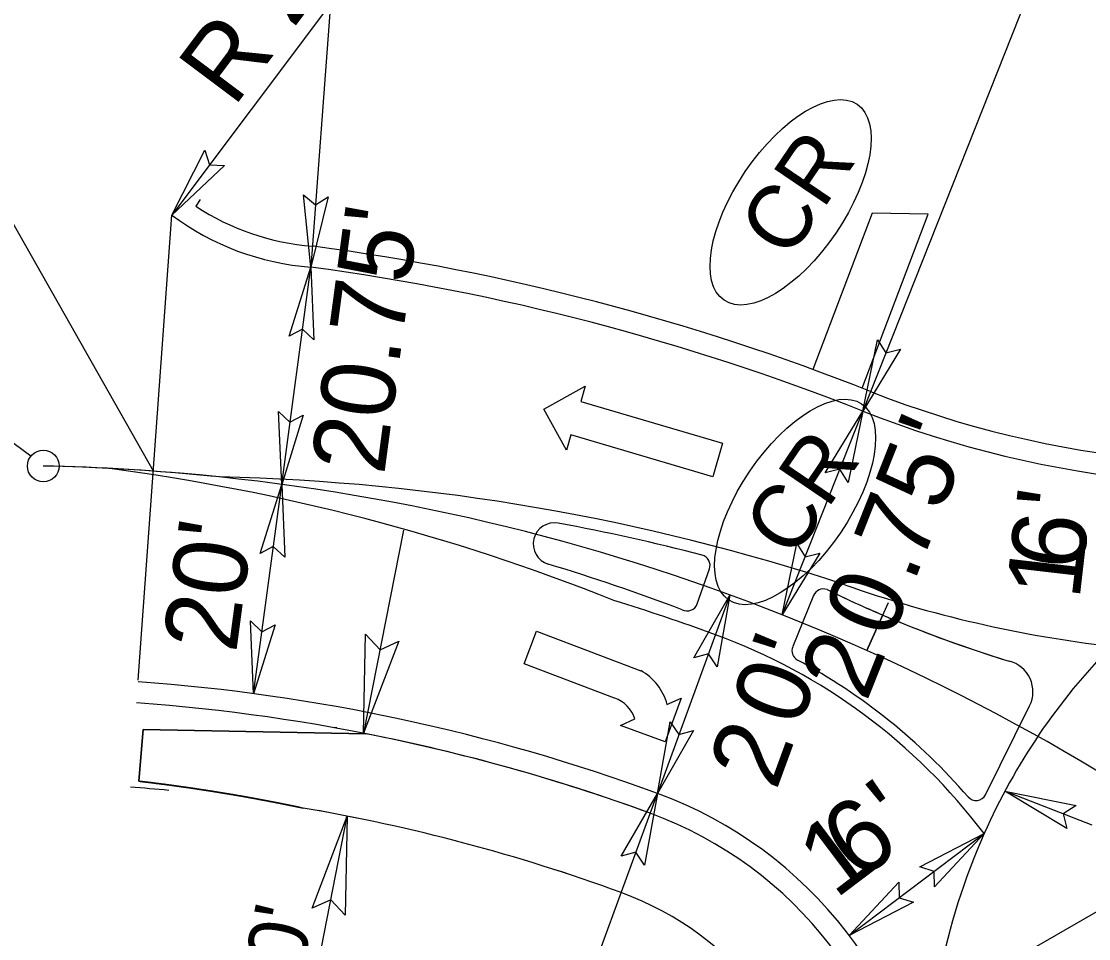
# Model space of a CAD drawing. Extents: x 1975573 to 1977432, y 778300 to 780514.
# Drawn here: x 1976181.7 to 1976308, y 779472 to 779580.6 of the extents above; entities that cross this region are included whole.
import ezdxf

# ---------------------------------------------------------------- set-up
doc = ezdxf.new("R2010")
doc.units = 0
for name, color, linetype in [('Prop Conc 2ft 6in Curb and Gutter', 7, 'Continuous'), ('Prop Conc 4in Sidewalk', 7, 'Continuous'), ('Prop Conc 5in Monolithic Keyed In Island', 7, 'Continuous'), ('Prop Dimension', 7, 'Continuous'), ('Prop Dimension Text', 7, 'Continuous'), ('Prop EOT', 7, 'Continuous'), ('Prop Horizontal Alignment', 7, 'Continuous'), ('Prop Horizontal Alignment Station Label', 7, 'Continuous'), ('Prop Horizontal Alignment Tick Small', 7, 'Continuous'), ('Prop Lane Arrow CELL', 7, 'Continuous'), ('Prop Lane Lines', 7, 'Continuous'), ('Prop Terminator CELL', 7, 'Continuous'), ('Prop WCC CELL', 7, 'Continuous'), ('Typical Terminator CELL', 7, 'Continuous')]:
    doc.layers.add(name, color=color, linetype=linetype)

# ---------------------------------------------------------------- blocks, each defined once
blk = doc.blocks.new('TERMINATOR')
at = {"layer": 'Typical Terminator CELL'}
blk.add_lwpolyline([(-0.4687, 0.0807), (0, 0), (-0.4713, -0.0833), (-0.4114, 0)], close=True, dxfattribs=at)

msp = doc.modelspace()

# ---------------------------------------------------------------- linework, layer by layer
at = {"layer": 'Prop Conc 2ft 6in Curb and Gutter'}
msp.add_line((1976202.88, 779559.51), (1976202.36, 779558.72), dxfattribs=at)
for centre, radius, start, end in [((1976218.28, 779582.67), 28.75, 236.3985, 265.7267), ((1976179.17, 779276.72), 279.73, 68.3898, 82.3776), ((1976327.31, 779650.68), 122.5, 248.3898, 280.6337), ((1976179.17, 779276.72), 223.8, 69.8927, 85.8568), ((1976239.78, 779442.27), 47.5, 5.4373, 69.8927)]:
    msp.add_arc(centre, radius, start, end, dxfattribs=at)
at = {"layer": 'Prop Conc 4in Sidewalk'}
for p, q in [((1976282.37, 779557.88), (1976275.36, 779539.4)), ((1976281.21, 779537.18), (1976289.01, 779557.77)), ((1976289.01, 779557.77), (1976282.37, 779557.88)), ((1976195.6, 779490.67), (1976196.11, 779496.78)), ((1976196.11, 779496.78), (1976195.6, 779490.67)), ((1976196.11, 779496.78), (1976222.47, 779496.29)), ((1976222.47, 779496.29), (1976196.11, 779496.78)), ((1976198.7, 779490.53), (1976198.7, 779490.53))]:
    msp.add_line(p, q, dxfattribs=at)
for centre, radius, start, end in [((1976179.17, 779276.72), 223.8, 69.8927, 78.8445), ((1976179.17, 779276.72), 223.8, 69.8927, 78.8445), ((1976179.17, 779276.72), 213.8, 84.6358, 85.8568), ((1976179.17, 779276.72), 213.8, 69.8927, 80.343), ((1976179.17, 779276.72), 213.8, 69.8927, 80.342), ((1976239.78, 779442.27), 47.5, 5.4373, 69.8927), ((1976239.78, 779442.27), 47.5, 5.4373, 69.8927), ((1976239.78, 779442.27), 37.5, 5.4373, 69.8927), ((1976239.78, 779442.27), 37.5, 5.4373, 69.8927)]:
    msp.add_arc(centre, radius, start, end, dxfattribs=at)
for points in [[(1976215.04, 779487.49), (1976214.87, 779487.53), (1976214.69, 779487.56), (1976214.52, 779487.6), (1976214.43, 779487.62), (1976214.35, 779487.63), (1976214.26, 779487.65), (1976214.17, 779487.67), (1976214.09, 779487.69), (1976214, 779487.71), (1976213.91, 779487.72), (1976213.83, 779487.74), (1976213.74, 779487.76), (1976213.65, 779487.78), (1976213.57, 779487.8), (1976213.48, 779487.81), (1976213.39, 779487.83), (1976213.31, 779487.85), (1976213.22, 779487.87), (1976213.13, 779487.88), (1976213.05, 779487.9), (1976212.96, 779487.92), (1976212.87, 779487.94), (1976212.78, 779487.95), (1976212.7, 779487.97), (1976212.61, 779487.99), (1976212.52, 779488), (1976212.44, 779488.02), (1976212.35, 779488.04), (1976212.26, 779488.06), (1976212.18, 779488.07), (1976212.09, 779488.09), (1976212, 779488.11), (1976211.91, 779488.12), (1976211.83, 779488.14), (1976211.74, 779488.16), (1976211.65, 779488.18), (1976211.57, 779488.19), (1976211.48, 779488.21), (1976211.39, 779488.23), (1976211.31, 779488.24), (1976211.22, 779488.26), (1976211.13, 779488.28), (1976211.04, 779488.29), (1976210.96, 779488.31), (1976210.87, 779488.33), (1976210.78, 779488.34), (1976210.7, 779488.36), (1976210.61, 779488.38), (1976210.52, 779488.39), (1976210.43, 779488.41), (1976210.35, 779488.43), (1976210.26, 779488.44), (1976210.17, 779488.46), (1976210.09, 779488.47), (1976210, 779488.49), (1976209.91, 779488.51), (1976209.82, 779488.52), (1976209.74, 779488.54), (1976209.65, 779488.56), (1976209.56, 779488.57), (1976209.48, 779488.59), (1976209.39, 779488.6), (1976209.3, 779488.62), (1976209.21, 779488.64), (1976209.13, 779488.65), (1976209.04, 779488.67), (1976208.95, 779488.68), (1976208.86, 779488.7), (1976208.78, 779488.71), (1976208.69, 779488.73), (1976208.6, 779488.75), (1976208.52, 779488.76), (1976208.43, 779488.78), (1976208.34, 779488.79), (1976208.25, 779488.81), (1976208.17, 779488.82), (1976208.08, 779488.84), (1976207.99, 779488.85), (1976207.9, 779488.87), (1976207.82, 779488.89), (1976207.73, 779488.9), (1976207.64, 779488.92), (1976207.55, 779488.93), (1976207.47, 779488.95), (1976207.38, 779488.96), (1976207.29, 779488.98), (1976207.2, 779488.99), (1976207.12, 779489.01), (1976207.03, 779489.02), (1976206.94, 779489.04), (1976206.86, 779489.05), (1976206.77, 779489.07), (1976206.68, 779489.08), (1976206.59, 779489.1), (1976206.51, 779489.11), (1976206.42, 779489.13), (1976206.33, 779489.14), (1976206.24, 779489.16), (1976206.16, 779489.17), (1976206.07, 779489.18), (1976205.98, 779489.2), (1976205.89, 779489.21), (1976205.8, 779489.23), (1976205.72, 779489.24), (1976205.63, 779489.26), (1976205.54, 779489.27), (1976205.45, 779489.29), (1976205.37, 779489.3), (1976205.28, 779489.31), (1976205.19, 779489.33), (1976205.1, 779489.34), (1976205.02, 779489.36), (1976204.93, 779489.37), (1976204.84, 779489.39), (1976204.75, 779489.4), (1976204.67, 779489.41), (1976204.58, 779489.43), (1976204.49, 779489.44), (1976204.4, 779489.46), (1976204.32, 779489.47), (1976204.23, 779489.48), (1976204.14, 779489.5), (1976204.05, 779489.51), (1976203.96, 779489.53), (1976203.88, 779489.54), (1976203.79, 779489.55), (1976203.7, 779489.57), (1976203.61, 779489.58), (1976203.53, 779489.59), (1976203.44, 779489.61), (1976203.35, 779489.62), (1976203.26, 779489.63), (1976203.18, 779489.65), (1976203.09, 779489.66), (1976203, 779489.67), (1976202.91, 779489.69), (1976202.82, 779489.7), (1976202.74, 779489.71), (1976202.65, 779489.73), (1976202.56, 779489.74), (1976202.47, 779489.75), (1976202.38, 779489.77), (1976202.3, 779489.78), (1976202.21, 779489.79), (1976202.12, 779489.81), (1976202.03, 779489.82), (1976201.95, 779489.83), (1976201.86, 779489.84), (1976201.77, 779489.86), (1976201.68, 779489.87), (1976201.59, 779489.88), (1976201.51, 779489.9), (1976201.42, 779489.91), (1976201.33, 779489.92), (1976201.24, 779489.93), (1976201.15, 779489.95), (1976201.07, 779489.96), (1976200.98, 779489.97), (1976200.89, 779489.98), (1976200.8, 779490), (1976200.71, 779490.01), (1976200.63, 779490.02), (1976200.54, 779490.03), (1976200.45, 779490.05), (1976200.36, 779490.06), (1976200.27, 779490.07), (1976200.19, 779490.08), (1976200.1, 779490.09), (1976200.01, 779490.11), (1976199.92, 779490.12), (1976199.83, 779490.13), (1976199.75, 779490.14), (1976199.66, 779490.16), (1976199.57, 779490.17), (1976199.48, 779490.18), (1976199.39, 779490.19), (1976199.31, 779490.2), (1976199.22, 779490.21), (1976199.13, 779490.23), (1976199.04, 779490.24), (1976198.95, 779490.25), (1976198.87, 779490.26), (1976198.78, 779490.27), (1976198.69, 779490.28), (1976198.6, 779490.3), (1976198.51, 779490.31), (1976198.43, 779490.32), (1976198.34, 779490.33), (1976198.25, 779490.34), (1976198.16, 779490.35), (1976198.07, 779490.36), (1976197.98, 779490.38), (1976197.9, 779490.39), (1976197.81, 779490.4), (1976197.72, 779490.41), (1976197.63, 779490.42), (1976197.54, 779490.43), (1976197.46, 779490.44), (1976197.37, 779490.45), (1976197.28, 779490.47), (1976197.19, 779490.48), (1976197.1, 779490.49), (1976197.01, 779490.5), (1976196.93, 779490.51), (1976196.84, 779490.52), (1976196.75, 779490.53), (1976196.66, 779490.54), (1976196.57, 779490.55), (1976196.49, 779490.56), (1976196.4, 779490.57), (1976196.31, 779490.58), (1976196.22, 779490.59), (1976196.13, 779490.6), (1976196.04, 779490.62), (1976195.96, 779490.63), (1976195.87, 779490.64), (1976195.78, 779490.65), (1976195.69, 779490.66), (1976195.6, 779490.67)], [(1976195.6, 779490.67), (1976195.69, 779490.66), (1976195.78, 779490.65), (1976195.87, 779490.64), (1976195.96, 779490.63), (1976196.04, 779490.62), (1976196.13, 779490.6), (1976196.22, 779490.59), (1976196.31, 779490.58), (1976196.4, 779490.57), (1976196.49, 779490.56), (1976196.57, 779490.55), (1976196.66, 779490.54), (1976196.75, 779490.53), (1976196.84, 779490.52), (1976196.93, 779490.51), (1976197.01, 779490.5), (1976197.1, 779490.49), (1976197.19, 779490.48), (1976197.28, 779490.47), (1976197.37, 779490.45), (1976197.46, 779490.44), (1976197.54, 779490.43), (1976197.63, 779490.42), (1976197.72, 779490.41), (1976197.81, 779490.4), (1976197.9, 779490.39), (1976197.98, 779490.38), (1976198.07, 779490.36), (1976198.16, 779490.35), (1976198.25, 779490.34), (1976198.34, 779490.33), (1976198.43, 779490.32), (1976198.51, 779490.31), (1976198.6, 779490.3), (1976198.69, 779490.28), (1976198.78, 779490.27), (1976198.87, 779490.26), (1976198.95, 779490.25), (1976199.04, 779490.24), (1976199.13, 779490.23), (1976199.22, 779490.21), (1976199.31, 779490.2), (1976199.39, 779490.19), (1976199.48, 779490.18), (1976199.57, 779490.17), (1976199.66, 779490.16), (1976199.75, 779490.14), (1976199.83, 779490.13), (1976199.92, 779490.12), (1976200.01, 779490.11), (1976200.1, 779490.09), (1976200.19, 779490.08), (1976200.27, 779490.07), (1976200.36, 779490.06), (1976200.45, 779490.05), (1976200.54, 779490.03), (1976200.63, 779490.02), (1976200.71, 779490.01), (1976200.8, 779490), (1976200.89, 779489.98), (1976200.98, 779489.97), (1976201.07, 779489.96), (1976201.15, 779489.95), (1976201.24, 779489.93), (1976201.33, 779489.92), (1976201.42, 779489.91), (1976201.51, 779489.9), (1976201.59, 779489.88), (1976201.68, 779489.87), (1976201.77, 779489.86), (1976201.86, 779489.84), (1976201.95, 779489.83), (1976202, 779489.82), (1976202.06, 779489.82), (1976202.11, 779489.81)], [(1976202.11, 779489.81), (1976202.15, 779489.8), (1976202.18, 779489.8), (1976202.21, 779489.79), (1976202.3, 779489.78), (1976202.38, 779489.77), (1976202.47, 779489.75), (1976202.56, 779489.74), (1976202.65, 779489.73), (1976202.74, 779489.71), (1976202.82, 779489.7), (1976202.91, 779489.69), (1976203, 779489.67), (1976203.09, 779489.66), (1976203.18, 779489.65), (1976203.26, 779489.63), (1976203.35, 779489.62), (1976203.44, 779489.61), (1976203.53, 779489.59), (1976203.61, 779489.58), (1976203.7, 779489.57), (1976203.79, 779489.55), (1976203.88, 779489.54), (1976203.96, 779489.53), (1976204.05, 779489.51), (1976204.14, 779489.5), (1976204.23, 779489.48), (1976204.32, 779489.47), (1976204.4, 779489.46), (1976204.49, 779489.44), (1976204.58, 779489.43), (1976204.67, 779489.41), (1976204.75, 779489.4), (1976204.84, 779489.39), (1976204.93, 779489.37), (1976205.02, 779489.36), (1976205.1, 779489.34), (1976205.19, 779489.33), (1976205.28, 779489.31), (1976205.37, 779489.3), (1976205.45, 779489.29), (1976205.54, 779489.27), (1976205.63, 779489.26), (1976205.72, 779489.24), (1976205.8, 779489.23), (1976205.89, 779489.21), (1976205.98, 779489.2), (1976206.07, 779489.18), (1976206.16, 779489.17), (1976206.24, 779489.16), (1976206.33, 779489.14), (1976206.42, 779489.13), (1976206.51, 779489.11), (1976206.59, 779489.1), (1976206.68, 779489.08), (1976206.77, 779489.07), (1976206.86, 779489.05), (1976206.94, 779489.04), (1976207.03, 779489.02), (1976207.12, 779489.01), (1976207.2, 779488.99), (1976207.29, 779488.98), (1976207.38, 779488.96), (1976207.47, 779488.95), (1976207.55, 779488.93), (1976207.64, 779488.92), (1976207.73, 779488.9), (1976207.82, 779488.89), (1976207.9, 779488.87), (1976207.99, 779488.85), (1976208.08, 779488.84), (1976208.17, 779488.82), (1976208.25, 779488.81), (1976208.34, 779488.79), (1976208.43, 779488.78), (1976208.52, 779488.76), (1976208.54, 779488.76), (1976208.57, 779488.75), (1976208.6, 779488.75)], [(1976208.6, 779488.75), (1976208.66, 779488.74), (1976208.72, 779488.73), (1976208.78, 779488.71), (1976208.86, 779488.7), (1976208.95, 779488.68), (1976209.04, 779488.67), (1976209.13, 779488.65), (1976209.21, 779488.64), (1976209.3, 779488.62), (1976209.39, 779488.6), (1976209.48, 779488.59), (1976209.56, 779488.57), (1976209.65, 779488.56), (1976209.74, 779488.54), (1976209.82, 779488.52), (1976209.91, 779488.51), (1976210, 779488.49), (1976210.09, 779488.47), (1976210.17, 779488.46), (1976210.26, 779488.44), (1976210.35, 779488.43), (1976210.43, 779488.41), (1976210.52, 779488.39), (1976210.61, 779488.38), (1976210.7, 779488.36), (1976210.78, 779488.34), (1976210.87, 779488.33), (1976210.96, 779488.31), (1976211.04, 779488.29), (1976211.13, 779488.28), (1976211.22, 779488.26), (1976211.31, 779488.24), (1976211.39, 779488.23), (1976211.48, 779488.21), (1976211.57, 779488.19), (1976211.65, 779488.18), (1976211.74, 779488.16), (1976211.83, 779488.14), (1976211.91, 779488.12), (1976212, 779488.11), (1976212.09, 779488.09), (1976212.18, 779488.07), (1976212.26, 779488.06), (1976212.35, 779488.04), (1976212.44, 779488.02), (1976212.52, 779488), (1976212.61, 779487.99), (1976212.7, 779487.97), (1976212.78, 779487.95), (1976212.87, 779487.94), (1976212.96, 779487.92), (1976213.05, 779487.9), (1976213.13, 779487.88), (1976213.22, 779487.87), (1976213.31, 779487.85), (1976213.39, 779487.83), (1976213.48, 779487.81), (1976213.57, 779487.8), (1976213.65, 779487.78), (1976213.74, 779487.76), (1976213.83, 779487.74), (1976213.91, 779487.72), (1976214, 779487.71), (1976214.09, 779487.69), (1976214.17, 779487.67), (1976214.26, 779487.65), (1976214.35, 779487.63), (1976214.43, 779487.62), (1976214.52, 779487.6), (1976214.69, 779487.56), (1976214.87, 779487.53), (1976215.04, 779487.49)]]:
    msp.add_open_spline(points, degree=3, dxfattribs=at)
at = {"layer": 'Prop Conc 5in Monolithic Keyed In Island'}
for p, q in [((1976261.67, 779511.64), (1976263.13, 779515.8)), ((1976275.46, 779512.64), (1976272.98, 779506.59)), ((1976295.8, 779489.07), (1976301.02, 779499.59))]:
    msp.add_line(p, q, dxfattribs=at)
for points in [[(1976261.67, 779511.64), (1976263.13, 779515.8)], [(1976275.46, 779512.64), (1976272.98, 779506.59)], [(1976283.64, 779510.34), (1976281.76, 779506.13), (1976283.64, 779510.34)], [(1976295.8, 779489.07), (1976301.02, 779499.59)]]:
    msp.add_lwpolyline(points, dxfattribs=at)
for centre, radius, start, end in [((1976244.78, 779518.75), 2.5, 79.4395, 253.1009), ((1976244.78, 779518.75), 2.5, 79.4395, 253.1009), ((1976198.82, 779272.22), 253.28, 75.4924, 79.4395), ((1976198.82, 779272.22), 253.28, 75.4924, 79.4395), ((1976261.95, 779516.21), 1.25, 340.6492, 75.4924), ((1976261.95, 779516.21), 1.25, 340.6492, 75.4924), ((1976171.22, 779276.62), 250.56, 69.2746, 73.1009), ((1976171.22, 779276.62), 250.56, 69.2746, 73.1009), ((1976276.61, 779512.17), 1.25, 69.8958, 157.7992), ((1976276.61, 779512.17), 1.25, 69.8958, 157.7992), ((1976341.8, 779646.63), 148.19, 244.0891, 253.0553), ((1976341.8, 779646.63), 148.19, 244.0891, 246.8935), ((1976260.5, 779512.06), 1.25, 241.0006, 340.6492), ((1976260.5, 779512.06), 1.25, 241.0006, 340.6492), ((1976341.8, 779646.63), 148.19, 246.8935, 253.0553), ((1976274.14, 779506.11), 1.25, 157.7992, 241.7102), ((1976274.14, 779506.11), 1.25, 157.7992, 241.7102), ((1976239.78, 779442.27), 71.25, 40.7773, 61.7102), ((1976239.78, 779442.27), 71.25, 40.7773, 61.7102), ((1976297.66, 779501.25), 3.75, 333.6015, 75.4103), ((1976297.66, 779501.25), 3.75, 333.6015, 75.4103), ((1976294.68, 779489.63), 1.25, 220.7773, 333.6015), ((1976294.68, 779489.63), 1.25, 220.7773, 333.6015)]:
    msp.add_arc(centre, radius, start, end, dxfattribs=at)
at = {"layer": 'Prop Dimension'}
for p, q in [((1976212.51, 779525.8), (1976215.95, 779551.51)), ((1976209.19, 779501.02), (1976212.51, 779525.8)), ((1976226.94, 779520.38), (1976222.2, 779496.34)), ((1976219.04, 779496.97), (1976218.77, 779497.02)), ((1976211, 779439.54), (1976220.27, 779486.53)), ((1976217.1, 779487.16), (1976216.83, 779487.21))]:
    msp.add_line(p, q, dxfattribs=at)
at = {"layer": 'Prop Dimension Text'}
for p, q in [((1976327.31, 779650.68), (1976281.28, 779534.47)), ((1976218.28, 779582.67), (1976199.52, 779557.67)), ((1976218.28, 779582.67), (1976215.95, 779551.51)), ((1976271.72, 779510.36), (1976281.28, 779534.47)), ((1976265.56, 779512.7), (1976256.97, 779489.23)), ((1976239.78, 779442.27), (1976256.97, 779489.23)), ((1976308.4, 779485.46), (1976298.09, 779489.5)), ((1976279.68, 779472.41), (1976295.63, 779484.47))]:
    msp.add_line(p, q, dxfattribs=at)
at = {"layer": 'Prop EOT'}
msp.add_line((1976195.54, 779502.62), (1976199.52, 779557.67), dxfattribs=at)
for centre, radius, start, end in [((1976218.28, 779582.67), 31.25, 233.1295, 265.7267), ((1976179.17, 779276.72), 277.23, 68.3898, 82.3776), ((1976327.31, 779650.68), 125, 248.3898, 280.6337), ((1976179.17, 779276.72), 226.3, 69.8927, 85.8568), ((1976239.78, 779442.27), 50, 5.4373, 69.8927)]:
    msp.add_arc(centre, radius, start, end, dxfattribs=at)
at = {"layer": 'Prop Horizontal Alignment'}
for centre, radius, start, end in [((1978303.2, 778082.63), 2375, 135.73946, 152.1381), ((1976179.17, 779276.72), 251.3, 55.1768, 88.8319), ((1976179.17, 779276.72), 251.3, 55.1768, 88.8319), ((1976179.17, 779276.72), 251.3, 55.1768, 88.8319), ((1976179.17, 779276.72), 251.3, 55.1768, 88.8319), ((1976179.17, 779276.72), 251.3, 55.1768, 88.8319)]:
    msp.add_arc(centre, radius, start, end, dxfattribs=at)
at = {"layer": 'Prop Horizontal Alignment Station Label'}
for p, q in [((1976197.33, 779527.36), (1976158.07, 779596.64)), ((1976182.82, 779529.12), (1976094.98, 779594.64)), ((1976321.01, 779482.16), (1976180.99, 779401.56))]:
    msp.add_line(p, q, dxfattribs=at)
msp.add_circle((1976184.3, 779527.97), 1.88, dxfattribs=at)
msp.add_circle((1976184.3, 779527.97), 1.88, dxfattribs=at)
at = {"layer": 'Prop Horizontal Alignment Tick Small'}
msp.add_line((1976281.76, 779506.13), (1976284.31, 779511.83), dxfattribs=at)
msp.add_line((1976281.76, 779506.13), (1976284.31, 779511.83), dxfattribs=at)
at = {"layer": 'Prop Lane Arrow CELL'}
for p, q in [((1976243.52, 779534.69), (1976248.43, 779537.41)), ((1976248.43, 779537.41), (1976247.9, 779535.61)), ((1976247.9, 779535.61), (1976264.69, 779530.66)), ((1976246.2, 779529.86), (1976243.52, 779534.69)), ((1976246.73, 779531.66), (1976246.2, 779529.86)), ((1976263.52, 779526.7), (1976246.73, 779531.66)), ((1976264.69, 779530.66), (1976263.52, 779526.7)), ((1976241.21, 779504.57), (1976242.68, 779508.43)), ((1976242.68, 779508.43), (1976255.01, 779503.73)), ((1976251.9, 779500.5), (1976241.21, 779504.57)), ((1976259.79, 779500.5), (1976257.89, 779495.34)), ((1976258.1, 779499.74), (1976259.79, 779500.5)), ((1976252.61, 779497.28), (1976254.31, 779498.04)), ((1976257.89, 779495.34), (1976252.61, 779497.28))]:
    msp.add_line(p, q, dxfattribs=at)
for centre, radius, start, end in [((1976251.78, 779498.04), 6.57, 15.1417, 60.4534), ((1976250.46, 779496.69), 4.09, 19.4713, 69.1294)]:
    msp.add_arc(centre, radius, start, end, dxfattribs=at)
at = {"layer": 'Prop Lane Lines'}
for centre, radius, start, end in [((1976179.17, 779276.72), 251.3, 84.2095, 88.8319), ((1976159.31, 779280.17), 249.67, 68.2497, 82.4998), ((1976199.38, 779272.11), 254.63, 71.7429, 88.6885), ((1976327.31, 779650.68), 145, 250.6014, 263.4132), ((1976179.17, 779276.72), 246.3, 69.8927, 72.8425), ((1976239.78, 779442.27), 70, 37.07, 69.8927), ((1976364.22, 779454.12), 75, 135.5489, 156.1292), ((1976364.16, 779453.7), 75.1, 155.8173, 182.5752)]:
    msp.add_arc(centre, radius, start, end, dxfattribs=at)
at = {"layer": 'Prop Terminator CELL'}
for points in [[(1976205.75, 779563.55), (1976199.52, 779557.67), (1976203.42, 779565.36), (1976203.97, 779563.6)], [(1976218.02, 779559.81), (1976215.95, 779551.51), (1976215.08, 779560.08), (1976216.5, 779558.89)], [(1976213.39, 779543.34), (1976215.95, 779551.51), (1976216.31, 779542.9), (1976214.96, 779544.17)], [(1976285.73, 779541.78), (1976281.28, 779534.47), (1976283.01, 779542.91), (1976284, 779541.36)], [(1976215.07, 779533.97), (1976212.51, 779525.8), (1976212.14, 779534.41), (1976213.49, 779533.14)], [(1976276.82, 779527.16), (1976281.28, 779534.47), (1976279.55, 779526.03), (1976278.55, 779527.58)], [(1976209.95, 779517.63), (1976212.51, 779525.8), (1976212.87, 779517.19), (1976211.52, 779518.46)], [(1976276.18, 779517.67), (1976271.72, 779510.36), (1976273.45, 779518.8), (1976274.45, 779517.24)], [(1976261.3, 779505.28), (1976265.56, 779512.7), (1976264.06, 779504.22), (1976263.02, 779505.75)], [(1976211.75, 779509.19), (1976209.19, 779501.02), (1976208.83, 779509.63), (1976210.17, 779508.36)], [(1976261.23, 779496.65), (1976256.97, 779489.23), (1976258.48, 779497.71), (1976259.52, 779496.18)], [(1976252.7, 779481.8), (1976256.97, 779489.23), (1976255.46, 779480.74), (1976254.42, 779482.27)], [(1976305.41, 779485.07), (1976298.09, 779489.5), (1976306.54, 779487.8), (1976304.98, 779486.8)], [(1976288.03, 779480.54), (1976295.63, 779484.47), (1976289.77, 779478.16), (1976289.72, 779480)], [(1976287.28, 779476.34), (1976279.68, 779472.41), (1976285.54, 779478.72), (1976285.59, 779476.88)]]:
    msp.add_lwpolyline(points, close=True, dxfattribs=at)
at = {"layer": 'Prop WCC CELL'}
for centre in [(1976272.73, 779559.18), (1976273.27, 779523.72)]:
    msp.add_ellipse(centre, major_axis=(7.87, 11.6), ratio=0.462467, dxfattribs=at)

# ---------------------------------------------------------------- block references
at = {"layer": 'Prop Dimension'}
for p, xscale, yscale, rotation in [((1976222.2, 779496.34), 24.500000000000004, 24.499999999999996, -101.15551934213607), ((1976220.27, 779486.53), 24.499999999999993, 24.499999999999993, 78.84448065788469)]:
    msp.add_blockref('TERMINATOR', p, dxfattribs=dict(at, xscale=xscale, yscale=yscale, rotation=rotation))

# ---------------------------------------------------------------- texts
msp.add_text("+54.60'", height=7, rotation=78.8445, dxfattribs=at).set_placement((1976210.46, 779445.08))
at = {"layer": 'Prop Dimension Text'}
for s, rotation, p in [("R 25'", 53.1295, (1976206.83, 779570.29)), ("20.75'", 82.3776, (1976224.63, 779526.8)), ("'", 68.3898, (1976293.38, 779529.4)), ('5', 68.3898, (1976290.59, 779522.35)), ('7', 68.3898, (1976288.16, 779516.2)), ("'", 83.4132, (1976308.1, 779522.42)), ('6', 83.4132, (1976307.29, 779515.44)), ("20'", 82.3776, (1976207.11, 779505.73)), ('1', 83.4132, (1976306.9, 779512.02)), ('.', 68.3898, (1976287.29, 779514.03)), ('0', 68.3898, (1976284.6, 779507.24)), ("'", 69.8927, (1976276.23, 779503.67)), ('2', 68.3898, (1976281.71, 779499.93)), ('0', 69.8927, (1976273.72, 779496.81)), ('2', 69.8927, (1976271.02, 779489.44)), ("'", 37.07, (1976286.36, 779482.95)), ('6', 37.07, (1976280.76, 779478.71)), ('1', 37.07, (1976278.01, 779476.64))]:
    msp.add_text(s, height=8.75, rotation=rotation, dxfattribs=at).set_placement(p)
at = {"layer": 'Prop WCC CELL'}
for p in [(1976272.48, 779552.23), (1976273.02, 779516.77)]:
    msp.add_text('CR', height=7.5, rotation=55.8441, dxfattribs=at).set_placement(p)

doc.saveas('drawing.dxf')
